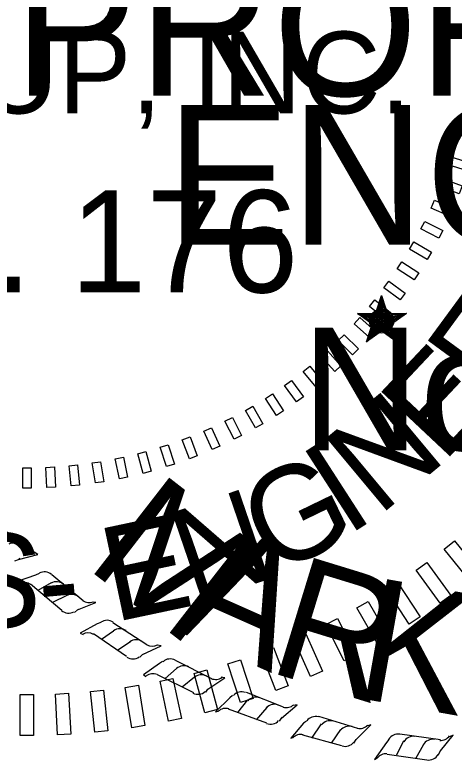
# Model space of a CAD drawing. Extents: x 1376650 to 1380188, y 377544 to 379765.
# Drawn here: x 1379910.8 to 1379972.3, y 377741.9 to 377846.2 of the extents above; entities that cross this region are included whole.
import ezdxf

# ---------------------------------------------------------------- set-up
doc = ezdxf.new("R2010")
doc.units = 0
doc.layers.add('Certificate of Authorization', color=7, linetype='Continuous')
doc.layers.add('R_Border PE', color=7, linetype='Continuous')

msp = doc.modelspace()

# ---------------------------------------------------------------- linework, layer by layer
at = {"layer": 'Certificate of Authorization'}
for points in [[(1379974.51, 377825.48), (1379974.15, 377824.36), (1379971.45, 377825.23), (1379971.81, 377826.35)], [(1379973.4, 377822.26), (1379972.98, 377821.16), (1379970.33, 377822.18), (1379970.75, 377823.28)], [(1379972.13, 377819.1), (1379971.65, 377818.03), (1379969.06, 377819.18), (1379969.54, 377820.26)], [(1379970.69, 377816.02), (1379970.16, 377814.97), (1379967.63, 377816.26), (1379968.16, 377817.31)], [(1379969.1, 377813.01), (1379968.51, 377811.99), (1379966.05, 377813.41), (1379966.64, 377814.43)], [(1379967.34, 377810.09), (1379966.7, 377809.11), (1379964.32, 377810.65), (1379964.96, 377811.64)], [(1379965.44, 377807.27), (1379964.75, 377806.32), (1379962.45, 377807.99), (1379963.15, 377808.94)], [(1379963.39, 377804.55), (1379962.65, 377803.64), (1379960.45, 377805.42), (1379961.19, 377806.34)], [(1379961.21, 377801.95), (1379960.42, 377801.07), (1379958.31, 377802.97), (1379959.1, 377803.84)], [(1379958.89, 377799.46), (1379958.05, 377798.62), (1379956.05, 377800.63), (1379956.88, 377801.46)], [(1379956.44, 377797.09), (1379955.57, 377796.3), (1379953.67, 377798.41), (1379954.54, 377799.2)], [(1379953.87, 377794.86), (1379952.96, 377794.12), (1379951.17, 377796.32), (1379952.09, 377797.06)], [(1379951.19, 377792.76), (1379950.24, 377792.07), (1379948.57, 377794.36), (1379949.52, 377795.06)], [(1379948.4, 377790.81), (1379947.42, 377790.17), (1379945.87, 377792.55), (1379946.86, 377793.19)], [(1379945.52, 377789), (1379944.5, 377788.42), (1379943.08, 377790.87), (1379944.1, 377791.46)], [(1379942.54, 377787.35), (1379941.49, 377786.82), (1379940.21, 377789.35), (1379941.25, 377789.88)], [(1379939.48, 377785.86), (1379938.41, 377785.38), (1379937.25, 377787.97), (1379938.33, 377788.45)], [(1379936.35, 377784.53), (1379935.25, 377784.11), (1379934.24, 377786.76), (1379935.33, 377787.18)], [(1379933.15, 377783.36), (1379932.03, 377783), (1379931.16, 377785.7), (1379932.28, 377786.06)], [(1379929.9, 377782.37), (1379928.76, 377782.06), (1379928.03, 377784.8), (1379929.16, 377785.11)], [(1379926.6, 377781.54), (1379925.45, 377781.3), (1379924.86, 377784.07), (1379926.01, 377784.32)], [(1379913.09, 377780), (1379911.92, 377780), (1379911.92, 377782.84), (1379913.09, 377782.84)], [(1379916.49, 377780.12), (1379915.32, 377780.06), (1379915.17, 377782.89), (1379916.35, 377782.95)], [(1379919.88, 377780.42), (1379918.72, 377780.29), (1379918.42, 377783.12), (1379919.59, 377783.24)], [(1379923.26, 377780.89), (1379922.09, 377780.71), (1379921.65, 377783.51), (1379922.81, 377783.69)], [(1379975.91, 377768.17), (1379974.48, 377767.01), (1379970.88, 377771.46), (1379972.31, 377772.62)], [(1379971.8, 377764.96), (1379970.31, 377763.88), (1379966.95, 377768.5), (1379968.44, 377769.59)], [(1379967.53, 377761.97), (1379965.98, 377760.96), (1379962.87, 377765.76), (1379964.42, 377766.76)], [(1379963.11, 377759.2), (1379961.51, 377758.28), (1379958.65, 377763.23), (1379960.25, 377764.15)], [(1379958.55, 377756.67), (1379956.91, 377755.83), (1379954.31, 377760.93), (1379955.95, 377761.76)], [(1379953.86, 377754.38), (1379952.18, 377753.63), (1379949.85, 377758.85), (1379951.54, 377759.6)], [(1379949.06, 377752.34), (1379947.34, 377751.68), (1379945.29, 377757.02), (1379947.01, 377757.68)], [(1379944.16, 377750.56), (1379942.41, 377749.99), (1379940.64, 377755.42), (1379942.4, 377755.99)], [(1379939.18, 377749.03), (1379937.4, 377748.55), (1379935.92, 377754.07), (1379937.7, 377754.55)], [(1379934.12, 377747.76), (1379932.31, 377747.38), (1379931.13, 377752.97), (1379932.93, 377753.36)], [(1379923.83, 377746.04), (1379922, 377745.84), (1379921.4, 377751.53), (1379923.24, 377751.72)], [(1379929, 377746.77), (1379927.18, 377746.48), (1379926.28, 377752.12), (1379928.1, 377752.41)], [(1379913.43, 377745.4), (1379911.58, 377745.4), (1379911.58, 377751.11), (1379913.43, 377751.11)], [(1379918.64, 377745.58), (1379916.8, 377745.48), (1379916.5, 377751.19), (1379918.34, 377751.29)]]:
    msp.add_lwpolyline(points, close=True, dxfattribs=at)
at = {"layer": 'R_Border PE'}
for p, q in [((1379962.13, 377806.92), (1379961.53, 377804.53)), ((1379962.13, 377806.92), (1379961.73, 377804.44)), ((1379962.13, 377806.92), (1379961.93, 377804.44)), ((1379962.13, 377803.34), (1379962.13, 377806.92)), ((1379962.13, 377806.92), (1379962.82, 377804.44)), ((1379962.13, 377806.92), (1379962.62, 377804.44)), ((1379962.13, 377806.92), (1379962.32, 377804.53)), ((1379958.75, 377804.44), (1379962.13, 377803.34)), ((1379958.75, 377804.44), (1379961.23, 377804.24)), ((1379958.75, 377804.44), (1379961.23, 377804.04)), ((1379958.75, 377804.44), (1379961.13, 377803.84)), ((1379958.75, 377804.44), (1379961.13, 377803.54)), ((1379958.75, 377804.44), (1379961.03, 377803.25)), ((1379958.75, 377804.44), (1379961.03, 377803.05)), ((1379965.6, 377804.44), (1379962.13, 377803.34)), ((1379965.6, 377804.44), (1379962.52, 377804.24)), ((1379965.6, 377804.44), (1379962.72, 377804.04)), ((1379965.6, 377804.44), (1379962.72, 377803.74)), ((1379965.6, 377804.44), (1379963.32, 377803.64)), ((1379965.6, 377804.44), (1379963.51, 377803.44)), ((1379965.6, 377804.44), (1379963.71, 377803.34)), ((1379960.04, 377800.47), (1379962.13, 377803.34)), ((1379960.04, 377800.47), (1379961.13, 377803.25)), ((1379960.04, 377800.47), (1379961.23, 377802.95)), ((1379960.04, 377800.47), (1379961.43, 377802.75)), ((1379964.21, 377800.47), (1379962.13, 377803.34)), ((1379964.21, 377800.47), (1379962.82, 377802.95)), ((1379964.21, 377800.47), (1379962.92, 377803.25)), ((1379964.21, 377800.47), (1379963.12, 377803.34)), ((1379960.04, 377800.47), (1379961.73, 377802.55)), ((1379960.04, 377800.47), (1379962.13, 377802.55)), ((1379960.04, 377800.47), (1379962.22, 377802.35)), ((1379964.21, 377800.47), (1379962.13, 377802.55)), ((1379964.21, 377800.47), (1379962.13, 377802.25)), ((1379964.21, 377800.47), (1379962.52, 377802.55)), ((1379908.26, 377775.37), (1379912.23, 377771.21)), ((1379911.34, 377770.02), (1379914.02, 377770.71)), ((1379914.02, 377770.71), (1379913.52, 377771.01)), ((1379910.84, 377769.82), (1379911.34, 377770.02)), ((1379911.34, 377770.02), (1379911.54, 377770.21)), ((1379913.72, 377767.83), (1379911.14, 377766.94)), ((1379914.22, 377768.03), (1379913.72, 377767.83)), ((1379916, 377767.93), (1379920.37, 377764.26)), ((1379911.14, 377766.94), (1379911.54, 377766.64)), ((1379917.39, 377762.87), (1379913.03, 377766.54)), ((1379915.9, 377766.74), (1379914.02, 377765.65)), ((1379918.08, 377764.96), (1379916.1, 377763.97)), ((1379922.15, 377763.97), (1379921.75, 377764.06)), ((1379919.57, 377762.97), (1379922.15, 377763.97)), ((1379919.57, 377762.97), (1379919.77, 377763.07)), ((1379919.18, 377762.58), (1379919.57, 377762.97)), ((1379922.35, 377760.99), (1379919.97, 377759.7)), ((1379922.85, 377761.19), (1379922.35, 377760.99)), ((1379924.53, 377761.19), (1379929.29, 377758.11)), ((1379924.63, 377760), (1379922.94, 377758.81)), ((1379919.97, 377759.7), (1379920.37, 377759.5)), ((1379926.42, 377756.43), (1379921.85, 377759.6)), ((1379927.01, 377758.51), (1379925.23, 377757.32)), ((1379928.7, 377756.72), (1379931.28, 377757.92)), ((1379931.28, 377757.92), (1379930.78, 377758.01)), ((1379928.7, 377756.72), (1379928.9, 377756.82)), ((1379928.3, 377756.33), (1379928.7, 377756.72)), ((1379931.48, 377755.73), (1379931.08, 377755.44)), ((1379933.26, 377755.93), (1379938.32, 377753.35)), ((1379931.08, 377755.44), (1379928.8, 377753.85)), ((1379933.46, 377754.74), (1379931.87, 377753.35)), ((1379928.8, 377753.85), (1379929.19, 377753.65)), ((1379935.84, 377751.37), (1379930.78, 377753.85)), ((1379935.94, 377753.55), (1379934.25, 377752.16)), ((1379937.82, 377751.86), (1379940.2, 377753.45)), ((1379940.2, 377753.45), (1379939.71, 377753.55)), ((1379937.53, 377751.47), (1379937.82, 377751.86)), ((1379937.82, 377751.86), (1379938.12, 377752.06)), ((1379940.9, 377750.67), (1379938.91, 377748.69)), ((1379941.29, 377750.97), (1379940.9, 377750.67)), ((1379943.18, 377751.47), (1379948.34, 377749.38)), ((1379943.38, 377750.38), (1379941.99, 377748.59)), ((1379948.14, 377747.8), (1379950.32, 377749.68)), ((1379950.32, 377749.68), (1379949.73, 377749.58)), ((1379938.91, 377748.69), (1379939.31, 377748.79)), ((1379946.06, 377747.1), (1379940.7, 377749.09)), ((1379946.06, 377749.29), (1379944.57, 377747.6)), ((1379947.84, 377747.4), (1379948.14, 377747.8)), ((1379948.14, 377747.8), (1379948.24, 377748)), ((1379951.61, 377747.4), (1379951.21, 377747.1)), ((1379953.3, 377748.1), (1379958.75, 377746.41)), ((1379951.21, 377747.1), (1379949.43, 377745.02)), ((1379953.69, 377747), (1379952.31, 377745.02)), ((1379958.55, 377744.82), (1379960.64, 377746.9)), ((1379960.64, 377746.9), (1379960.04, 377746.71)), ((1379956.57, 377743.93), (1379951.11, 377745.42)), ((1379956.37, 377746.21), (1379955.08, 377744.33)), ((1379964.7, 377745.62), (1379970.36, 377744.82)), ((1379970.36, 377743.23), (1379972.14, 377745.42)), ((1379972.14, 377745.42), (1379971.65, 377745.22)), ((1379949.43, 377745.02), (1379949.73, 377745.12)), ((1379958.26, 377744.33), (1379958.55, 377744.82)), ((1379958.55, 377744.82), (1379958.75, 377745.02)), ((1379962.82, 377744.43), (1379961.13, 377742.04)), ((1379963.12, 377744.82), (1379962.82, 377744.43)), ((1379965.2, 377744.62), (1379964.21, 377742.64)), ((1379967.98, 377744.13), (1379966.89, 377742.14)), ((1379970.06, 377742.64), (1379970.36, 377743.23)), ((1379970.36, 377743.23), (1379970.46, 377743.43)), ((1379961.13, 377742.04), (1379961.53, 377742.24)), ((1379968.47, 377741.95), (1379962.92, 377742.74))]:
    msp.add_line(p, q, dxfattribs=at)
msp.add_lwpolyline([(1379962.13, 377806.92), (1379964.21, 377800.47), (1379958.75, 377804.44), (1379965.6, 377804.44), (1379960.04, 377800.47), (1379962.13, 377806.92)], dxfattribs=at)
for radius in [1.68, 1.52, 1.41, 1.3, 1.13, 1.05, 0.967, 0.833, 0.73, 0.607, 0.484, 0.361, 0.289, 0.141]:
    msp.add_circle((1379962.13, 377803.37), radius, dxfattribs=at)
for centre, start, end in [((1379910.57, 377770.75), 44.9655, 113.3394), ((1379913.19, 377772.45), 229.2262, 288.0141), ((1379914.98, 377766.73), 50.1902, 118.5642), ((1379912.12, 377765.25), 54.451, 113.2388), ((1379916.63, 377765.36), 50.1902, 118.5642), ((1379918.74, 377763.59), 50.1902, 118.5642), ((1379921.19, 377765.52), 234.451, 293.2388), ((1379918.34, 377764.04), 230.1902, 298.5642), ((1379923.74, 377759.96), 56.1736, 124.5476), ((1379925.52, 377758.78), 56.1736, 124.5476), ((1379921.05, 377758.19), 60.4344, 119.2222), ((1379927.8, 377757.23), 56.1736, 124.5476), ((1379930.04, 377759.41), 240.4344, 299.2222), ((1379927.35, 377757.64), 236.1736, 304.5476), ((1379932.57, 377754.56), 63.0708, 131.4448), ((1379934.48, 377753.6), 63.0708, 131.4448), ((1379930.12, 377752.48), 67.3316, 126.1194), ((1379936.93, 377752.34), 63.0708, 131.4448), ((1379938.9, 377754.77), 247.3316, 306.1194), ((1379936.44, 377752.69), 243.0708, 311.4448), ((1379942.54, 377749.96), 69.0955, 137.4695), ((1379944.54, 377749.2), 69.0955, 137.4695), ((1379947.11, 377748.21), 69.0955, 137.4695), ((1379948.81, 377750.83), 253.3563, 312.1441), ((1379940.32, 377747.64), 73.3563, 132.1441), ((1379946.59, 377748.51), 249.0955, 317.4695), ((1379952.87, 377746.5), 73.9909, 142.3649), ((1379954.92, 377745.92), 73.9909, 142.3649), ((1379957.57, 377745.15), 73.9909, 142.3649), ((1379959.04, 377747.9), 258.2517, 317.0395), ((1379950.85, 377743.99), 78.2517, 137.0395), ((1379964.45, 377744.05), 81.4231, 149.797), ((1379970.39, 377746.24), 265.6839, 324.4717), ((1379957.02, 377745.4), 253.9909, 322.3649), ((1379966.57, 377743.73), 81.4231, 149.797), ((1379969.29, 377743.31), 81.4231, 149.797), ((1379962.77, 377741.3), 85.6839, 144.4717), ((1379968.71, 377743.49), 261.4231, 329.797)]:
    msp.add_arc(centre, 1.54, start, end, dxfattribs=at)

# ---------------------------------------------------------------- texts
at = {"layer": 'Certificate of Authorization'}
for s, height, p in [('GROUP, INC.', 11.4468, (1379870.98, 377832.41)), ('No. 176', 14.307, (1379883.47, 377807.36))]:
    msp.add_text(s, height=height, dxfattribs=at).set_placement(p)
for s, rotation, p in [('E', 53.7169, (1379978.38, 377791.66)), ('E', 46.7552, (1379970.71, 377783.38)), ('N', 39.7936, (1379961.72, 377775.95)), ('I', 32.8319, (1379957.29, 377773.2)), ('G', 25.8703, (1379946.86, 377767.68)), ('N', 18.9086, (1379935.71, 377763.61)), ('E', 11.9469, (1379924.68, 377761.21)), ('S', 358.0236, (1379902.62, 377760.73)), ('-', 4.9853, (1379914.49, 377760.37))]:
    msp.add_text(s, height=13.19, rotation=rotation, dxfattribs=at).set_placement(p)
at = {"layer": 'R_Border PE'}
for s, height, p in [('PROFESSIONAL', 19.5249, (1379910.64, 377834.89)), ('ENGINEER', 19.525, (1379931.97, 377814.06)), ('No. 8940', 17.153, (1379950.92, 377785.29))]:
    msp.add_text(s, height=height, dxfattribs=at).set_placement(p)
for s, rotation, p in [('M', 322.1623, (1379920.46, 377769.12)), ('A', 336.0227, (1379932.86, 377760.3)), ('R', 342.9529, (1379945.86, 377754.44)), ('K', 349.8831, (1379958.06, 377750.77))]:
    msp.add_text(s, height=17.08, rotation=rotation, dxfattribs=at).set_placement(p)

doc.saveas('drawing.dxf')
